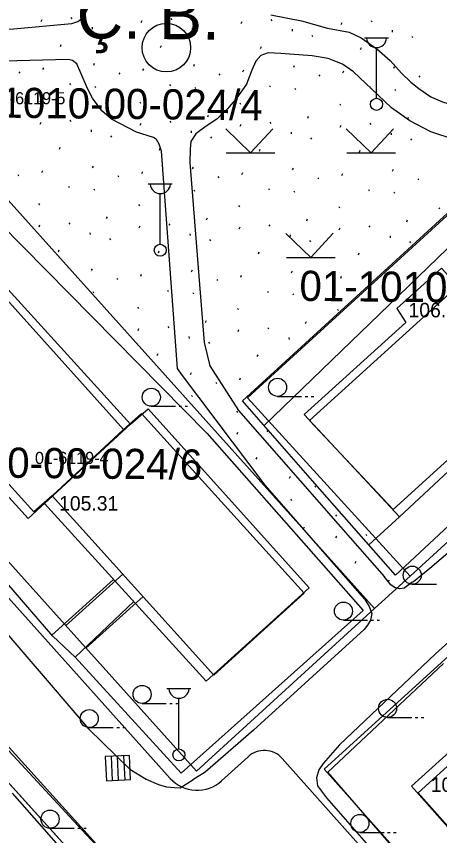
# Model space of a CAD drawing. Extents: x 412225 to 413380, y 4456471 to 4457189.
# Drawn here: x 412615.8 to 412650.9, y 4457061.2 to 4457129.1 of the extents above; entities that cross this region are included whole.
import ezdxf

# ---------------------------------------------------------------- set-up
doc = ezdxf.new("R2010")
doc.units = 0
for name, color, linetype in [('0_HALİHAZIR', 7, 'Continuous'), ('0_KADASTRO', 7, 'Continuous'), ('Level 27', 7, 'Continuous'), ('Level 41', 7, 'Continuous'), ('Level 56', 7, 'Continuous'), ('Level 57', 7, 'Continuous'), ('Level 59', 7, 'Continuous'), ('Level 62', 7, 'Continuous')]:
    doc.layers.add(name, color=color, linetype=linetype)

msp = doc.modelspace()

# ---------------------------------------------------------------- linework, layer by layer
at = {"layer": '0_HALİHAZIR'}
for p, q in [((412644.653, 4457127.279), (412646.653, 4457127.279)), ((412645.653, 4457122.279), (412645.653, 4457126.472)), ((412635.207, 4457117.747), (412633.147, 4457119.737)), ((412635.207, 4457117.747), (412637.057, 4457119.757)), ((412645.207, 4457117.748), (412643.147, 4457119.738)), ((412645.207, 4457117.748), (412647.057, 4457119.758)), ((412633.187, 4457117.747), (412637.227, 4457117.747)), ((412643.187, 4457117.748), (412647.227, 4457117.748)), ((412626.723, 4457115.185), (412628.723, 4457115.185)), ((412627.723, 4457110.185), (412627.723, 4457114.378)), ((412640.208, 4457109.087), (412638.148, 4457111.077)), ((412640.208, 4457109.087), (412642.058, 4457111.098)), ((412638.188, 4457109.087), (412642.228, 4457109.088)), ((412637.447, 4457097.584), (412639.447, 4457097.584)), ((412639.747, 4457097.584), (412639.947, 4457097.584)), ((412640.247, 4457097.584), (412640.447, 4457097.584)), ((412626.98, 4457096.761), (412628.98, 4457096.761)), ((412629.28, 4457096.761), (412629.48, 4457096.761)), ((412629.78, 4457096.761), (412629.98, 4457096.761)), ((412648.619, 4457082.016), (412650.619, 4457082.016)), ((412642.909, 4457079.04), (412644.909, 4457079.04)), ((412645.209, 4457079.04), (412645.409, 4457079.04)), ((412645.709, 4457079.04), (412645.909, 4457079.04)), ((412628.271, 4457073.374), (412630.271, 4457073.374)), ((412629.271, 4457068.374), (412629.271, 4457072.567)), ((412626.215, 4457072.141), (412628.215, 4457072.142)), ((412628.515, 4457072.142), (412628.715, 4457072.142)), ((412629.015, 4457072.142), (412629.215, 4457072.142)), ((412646.57, 4457070.983), (412648.57, 4457070.983)), ((412648.87, 4457070.983), (412649.07, 4457070.983)), ((412649.37, 4457070.983), (412649.57, 4457070.983)), ((412621.832, 4457070.135), (412623.832, 4457070.135)), ((412624.132, 4457070.135), (412624.332, 4457070.135)), ((412624.632, 4457070.135), (412624.832, 4457070.135)), ((412625.164, 4457067.837), (412623.166, 4457067.732)), ((412625.164, 4457067.837), (412623.166, 4457067.732)), ((412624.271, 4457065.787), (412624.165, 4457067.784)), ((412624.818, 4457065.816), (412624.712, 4457067.813)), ((412625.269, 4457065.84), (412625.164, 4457067.837)), ((412625.269, 4457065.84), (412625.164, 4457067.837)), ((412623.166, 4457067.732), (412623.272, 4457065.734)), ((412623.166, 4457067.732), (412623.272, 4457065.734)), ((412623.776, 4457065.761), (412623.67, 4457067.758)), ((412623.272, 4457065.734), (412625.269, 4457065.84)), ((412623.272, 4457065.734), (412625.269, 4457065.84)), ((412618.582, 4457061.803), (412620.582, 4457061.803)), ((412620.882, 4457061.803), (412621.082, 4457061.803)), ((412621.382, 4457061.803), (412621.582, 4457061.803)), ((412644.276, 4457061.448), (412646.276, 4457061.448)), ((412646.576, 4457061.448), (412646.776, 4457061.448)), ((412647.076, 4457061.448), (412647.276, 4457061.448))]:
    msp.add_line(p, q, dxfattribs=at)
for points in [[(412666.722, 4457149.847), (412683.715, 4457130.465), (412688.733, 4457125.108), (412689.962, 4457123.702), (412690.595, 4457122.882), (412690.735, 4457122.493), (412690.726, 4457122.1), (412690.676, 4457121.39), (412690.163, 4457120.297), (412689.764, 4457119.716), (412687.857, 4457117.849), (412679.792, 4457110.22), (412668.162, 4457099.827), (412652.892, 4457085.728), (412650.071, 4457083.307)], [(412586.499, 4457113.505), (412599.497, 4457125.36), (412601.397, 4457126.977), (412602.133, 4457127.316), (412602.666, 4457127.482), (412615.554, 4457128.043), (412620.399, 4457128.469), (412620.895, 4457128.65), (412621.301, 4457128.945), (412621.489, 4457129.276), (412621.709, 4457129.751), (412622.347, 4457130.765), (412623.233, 4457131.631), (412624.368, 4457132.606), (412625.456, 4457133.146), (412626.053, 4457133.394), (412626.466, 4457133.835), (412626.657, 4457134.458), (412626.648, 4457144.638), (412626.453, 4457148.095), (412625.97, 4457149.047)], [(412636.89, 4457129.185), (412639.421, 4457128.686), (412641.594, 4457128.096), (412643.378, 4457127.758), (412644.388, 4457127.291), (412645.679, 4457126.37), (412646.785, 4457125.411), (412647.716, 4457124.363), (412648.493, 4457123.616), (412649.171, 4457123.093), (412650.158, 4457122.408), (412651.134, 4457121.991), (412652.439, 4457121.569), (412653.902, 4457121.37), (412655.306, 4457121.661), (412656.704, 4457122.549), (412667.092, 4457132.24)], [(412571.237, 4457126.583), (412582.789, 4457113.858), (412594.87, 4457100.897), (412607.242, 4457086.936), (412618.505, 4457073.845), (412621.76, 4457070.045)], [(412656.443, 4457091.342), (412647.227, 4457082.781), (412640.333, 4457090.585), (412634.547, 4457097.223), (412666.876, 4457126.785)], [(412644.651, 4457080.814), (412636.43, 4457090.235), (412629.579, 4457099.303), (412629.159, 4457099.886), (412627.822, 4457117.893), (412627.634, 4457118.487), (412627.411, 4457118.876), (412627.164, 4457119.036), (412625.749, 4457119.464), (412623.688, 4457120.559), (412622.872, 4457121.235), (412622.111, 4457122.274), (412621.691, 4457123.088), (412620.8, 4457125.119), (412620.449, 4457125.394), (412620.125, 4457125.484), (412605.091, 4457125.109), (412603.566, 4457124.813), (412601.564, 4457123.567), (412588.315, 4457111.518)], [(412652.173, 4457118.831), (412650.162, 4457119.485), (412648.408, 4457120.406), (412646.907, 4457121.484), (412645.248, 4457123.057), (412643.753, 4457124.475), (412642.836, 4457125.096), (412641.644, 4457125.585), (412640.327, 4457125.789), (412637.72, 4457125.987), (412636.663, 4457126.043), (412636.055, 4457125.832), (412635.653, 4457125.354), (412635.308, 4457124.593), (412634.882, 4457123.446), (412634.08, 4457122.32), (412633.301, 4457121.411), (412632.403, 4457120.545), (412631.52, 4457119.959), (412630.659, 4457119.335), (412630.272, 4457118.698), (412630.191, 4457118.081), (412630.167, 4457116.95), (412630.912, 4457107.534), (412631.365, 4457102.055), (412631.823, 4457100.119), (412634.208, 4457096.413), (412642.673, 4457086.772), (412646.278, 4457082.661)], [(412668.291, 4457125.985), (412636.342, 4457095.163)], [(412610.607, 4457115.774), (412631.597, 4457094.524), (412644.556, 4457079.848), (412629.451, 4457066.363), (412620.68, 4457075.971)], [(412688.789, 4457110.474), (412676.857, 4457100.196), (412663.153, 4457087.564), (412650.553, 4457076.263), (412642.59, 4457068.703), (412641.23, 4457067.176), (412640.87, 4457066.641), (412640.687, 4457065.987), (412640.751, 4457065.319), (412641.497, 4457064.308), (412651.959, 4457052.379)], [(412618.823, 4457077.701), (412607.347, 4457090.959)], [(412662.749, 4457016.406), (412651.562, 4457029.05), (412636.523, 4457045.377), (412621.572, 4457061.282), (412605.727, 4457078.415), (412597.001, 4457088.077)], [(412647.572, 4457087.605), (412645.027, 4457085.271)], [(412650.071, 4457083.307), (412648.709, 4457082.211), (412648.553, 4457082.163)], [(412618.742, 4457077.795), (412623.857, 4457082.42)], [(412648.553, 4457082.163), (412647.968, 4457081.695), (412647.564, 4457081.643), (412647.142, 4457081.739), (412646.838, 4457081.974), (412646.278, 4457082.661)], [(412644.651, 4457080.814), (412645.047, 4457080.166), (412645.263, 4457079.601), (412645.16, 4457079.041), (412644.916, 4457078.623), (412644.639, 4457078.257), (412635.466, 4457069.923), (412631.434, 4457066.459), (412630.426, 4457065.824)], [(412620.68, 4457075.971), (412625.519, 4457080.591)], [(412618.823, 4457077.701), (412620.68, 4457075.971)], [(412654.345, 4457051.812), (412641.626, 4457066.439), (412651.198, 4457075.443)], [(412621.76, 4457070.045), (412625.211, 4457066.702), (412626.558, 4457065.881), (412627.566, 4457065.421), (412628.233, 4457065.239), (412628.893, 4457065.167), (412629.36, 4457065.154), (412630.426, 4457065.824)], [(412615.442, 4457064.702), (412625.563, 4457053.22), (412611.173, 4457039.673), (412592.706, 4457059.584), (412594.529, 4457061.141)]]:
    msp.add_lwpolyline(points, dxfattribs=at)
for points in [[(412611.765, 4457110.092), (412625.266, 4457095.29), (412616.766, 4457087.459), (412603.258, 4457102.358)], [(412654.493, 4457109.584), (412651.817, 4457107.339), (412651.035, 4457108.208), (412647.338, 4457104.848), (412648.093, 4457103.7), (412639.667, 4457096.084), (412647.572, 4457087.605), (412662.236, 4457101.272), (412660.946, 4457102.707)], [(412625.266, 4457095.29), (412626.708, 4457096.541), (412640.062, 4457081.722), (412631.519, 4457073.991), (412618.132, 4457088.717)], [(412663.445, 4457078.735), (412669.857, 4457071.607), (412671.07, 4457070.131), (412656.277, 4457056.58), (412648.567, 4457065.292)]]:
    msp.add_lwpolyline(points, close=True, dxfattribs=at)
for centre, radius in [((412628.231, 4457126.47), 2.009), ((412645.653, 4457121.779), 0.5), ((412627.723, 4457109.685), 0.5), ((412637.447, 4457098.334), 0.75), ((412626.98, 4457097.511), 0.75), ((412648.619, 4457082.766), 0.75), ((412642.909, 4457079.79), 0.75), ((412626.215, 4457072.891), 0.75), ((412646.57, 4457071.733), 0.75), ((412621.832, 4457070.885), 0.75), ((412629.271, 4457067.874), 0.5), ((412618.582, 4457062.553), 0.75), ((412644.276, 4457062.198), 0.75)]:
    msp.add_circle(centre, radius, dxfattribs=at)
for centre in [(412645.653, 4457127.309), (412627.723, 4457115.215), (412629.271, 4457073.403)]:
    msp.add_arc(centre, 0.837, 183.298, 356.90719, dxfattribs=at)
at = {"layer": '0_KADASTRO'}
msp.add_lwpolyline([(412602.001, 4457142.229), (412625.676, 4457149.845), (412628.236, 4457150.669), (412623.56, 4457165.205), (412628.608, 4457159.498), (412642.417, 4457143.887), (412658.161, 4457126.088), (412659.073, 4457125.057), (412673.936, 4457138.44), (412689.844, 4457120.47), (412682.426, 4457113.701), (412681.983, 4457114.187), (412668.946, 4457128.476), (412634.964, 4457097.471), (412647.897, 4457083.297), (412648.445, 4457082.697), (412645.49, 4457080.001), (412613.407, 4457115.704)], dxfattribs=at)
for points in [[(412634.964, 4457097.471), (412668.946, 4457128.476), (412681.983, 4457114.187), (412682.426, 4457113.701), (412648.445, 4457082.697), (412647.897, 4457083.297)], [(412598.633, 4457102.224), (412612.968, 4457115.303), (412613.407, 4457115.704), (412645.49, 4457080.001), (412630.715, 4457066.521), (412613.994, 4457085.129)], [(412641.315, 4457066.687), (412676.859, 4457098.984), (412677.17, 4457098.634), (412690.156, 4457084.044), (412672.943, 4457068.403), (412654.627, 4457051.76), (412641.805, 4457066.138)], [(412576.154, 4457078.845), (412590.151, 4457091.291), (412591.099, 4457092.135), (412625.322, 4457054.321), (412625.104, 4457054.128), (412610.332, 4457040.992), (412593.199, 4457059.967), (412576.633, 4457078.314)]]:
    msp.add_lwpolyline(points, close=True, dxfattribs=at)
at = {"layer": 'Level 27'}
for points in [[(412630.715, 4457066.521), (412613.994, 4457085.129), (412598.633, 4457102.224), (412597.284, 4457103.724), (412561.903, 4457143.098), (412560.367, 4457144.807)], [(412689.844, 4457120.47), (412682.426, 4457113.701), (412648.445, 4457082.697), (412645.49, 4457080.001), (412645.49, 4457080.001), (412630.715, 4457066.521)], [(412641.315, 4457066.687), (412676.859, 4457098.984), (412679.801, 4457101.657), (412694.484, 4457115.229)], [(412592.561, 4457090.519), (412625.322, 4457054.321), (412632.032, 4457046.907), (412649.43, 4457027.697), (412649.43, 4457027.697), (412668.449, 4457006.699), (412669.615, 4457004.71), (412669.079, 4457002.597), (412668.196, 4457000.596), (412654.558, 4456991.925), (412647.057, 4456987.08), (412625.215, 4456972.976), (412617.864, 4456968.23), (412604.785, 4456959.819), (412602.573, 4456958.764), (412600.503, 4456958.758), (412598.437, 4456960.001), (412566.106, 4456995.183), (412565.155, 4456996.219), (412533.021, 4457031.187), (412532.637, 4457031.604)], [(412745.985, 4457051.286), (412744.84, 4457050.509), (412726.191, 4457038.285), (412705.949, 4457025.019), (412705.176, 4457024.512), (412701.293, 4457021.967), (412698.715, 4457020.277), (412686.613, 4457012.33), (412683.807, 4457011.528), (412680.955, 4457012.103), (412678.505, 4457013.338), (412651.296, 4457043.314), (412648.699, 4457046.374), (412649.306, 4457046.925), (412654.025, 4457051.213), (412654.627, 4457051.76), (412641.805, 4457066.138), (412641.315, 4457066.687)]]:
    msp.add_lwpolyline(points, dxfattribs=at)
at = {"layer": 'Level 41'}
for p, q in [((412620.32, 4457128.971), (412620.39, 4457128.863)), ((412628.613, 4457128.886), (412628.683, 4457128.778)), ((412617.852, 4457128.651), (412617.925, 4457128.81)), ((412626.144, 4457128.566), (412626.218, 4457128.725)), ((412634.437, 4457128.481), (412634.511, 4457128.641)), ((412636.905, 4457128.801), (412636.975, 4457128.693)), ((412642.73, 4457128.396), (412642.803, 4457128.556)), ((412645.198, 4457128.716), (412645.268, 4457128.608)), ((412622.07, 4457128.162), (412622.086, 4457128.002)), ((412623.695, 4457127.675), (412623.764, 4457127.567)), ((412630.363, 4457128.077), (412630.379, 4457127.917)), ((412631.988, 4457127.59), (412632.057, 4457127.483)), ((412638.655, 4457127.992), (412638.672, 4457127.832)), ((412640.28, 4457127.505), (412640.349, 4457127.398)), ((412646.948, 4457127.907), (412646.964, 4457127.747)), ((412648.573, 4457127.421), (412648.642, 4457127.313)), ((412619.447, 4457126.575), (412619.52, 4457126.734)), ((412627.739, 4457126.49), (412627.813, 4457126.649)), ((412636.032, 4457126.405), (412636.105, 4457126.564)), ((412644.324, 4457126.32), (412644.398, 4457126.479)), ((412617.989, 4457124.651), (412618.062, 4457124.811)), ((412622.203, 4457125.016), (412622.274, 4457125.176)), ((412630.495, 4457124.931), (412630.567, 4457125.091)), ((412638.788, 4457124.847), (412638.86, 4457125.006)), ((412647.081, 4457124.762), (412647.152, 4457124.921)), ((412615.999, 4457124.464), (412616.069, 4457124.357)), ((412624.291, 4457124.379), (412624.361, 4457124.272)), ((412626.281, 4457124.567), (412626.354, 4457124.726)), ((412632.584, 4457124.294), (412632.654, 4457124.187)), ((412634.574, 4457124.482), (412634.647, 4457124.641)), ((412640.877, 4457124.209), (412640.946, 4457124.102)), ((412642.867, 4457124.397), (412642.939, 4457124.556)), ((412649.169, 4457124.124), (412649.239, 4457124.018)), ((412620.197, 4457123.492), (412620.267, 4457123.384)), ((412622.294, 4457123.278), (412622.364, 4457123.171)), ((412628.49, 4457123.407), (412628.56, 4457123.299)), ((412630.587, 4457123.193), (412630.657, 4457123.086)), ((412636.782, 4457123.322), (412636.852, 4457123.214)), ((412638.879, 4457123.109), (412638.949, 4457123.001)), ((412645.075, 4457123.237), (412645.145, 4457123.129)), ((412647.172, 4457123.024), (412647.242, 4457122.916)), ((412617.726, 4457122.064), (412617.796, 4457121.956)), ((412626.019, 4457121.979), (412626.089, 4457121.871)), ((412634.312, 4457121.894), (412634.381, 4457121.786)), ((412642.604, 4457121.809), (412642.674, 4457121.702)), ((412623.366, 4457120.813), (412623.439, 4457120.971)), ((412631.658, 4457120.728), (412631.731, 4457120.887)), ((412639.951, 4457120.643), (412640.024, 4457120.802)), ((412648.244, 4457120.559), (412648.316, 4457120.717)), ((412617.765, 4457120.141), (412617.838, 4457120.301)), ((412620.233, 4457120.461), (412620.303, 4457120.353)), ((412626.057, 4457120.057), (412626.131, 4457120.216)), ((412628.526, 4457120.376), (412628.596, 4457120.269)), ((412634.35, 4457119.972), (412634.423, 4457120.131)), ((412636.818, 4457120.291), (412636.888, 4457120.184)), ((412642.642, 4457119.887), (412642.716, 4457120.046)), ((412645.111, 4457120.207), (412645.181, 4457120.099)), ((412621.983, 4457119.652), (412621.999, 4457119.492)), ((412630.275, 4457119.567), (412630.292, 4457119.407)), ((412638.568, 4457119.483), (412638.584, 4457119.322)), ((412646.861, 4457119.398), (412646.877, 4457119.237)), ((412623.608, 4457119.166), (412623.677, 4457119.058)), ((412631.901, 4457119.081), (412631.97, 4457118.973)), ((412640.193, 4457118.996), (412640.262, 4457118.888)), ((412648.486, 4457118.911), (412648.555, 4457118.803)), ((412619.36, 4457118.065), (412619.433, 4457118.224)), ((412627.652, 4457117.98), (412627.726, 4457118.139)), ((412635.945, 4457117.895), (412636.018, 4457118.055)), ((412644.237, 4457117.81), (412644.311, 4457117.97)), ((412622.116, 4457116.507), (412622.187, 4457116.666)), ((412615.912, 4457115.954), (412615.982, 4457115.847)), ((412617.902, 4457116.142), (412617.974, 4457116.301)), ((412626.194, 4457116.057), (412626.267, 4457116.216)), ((412630.408, 4457116.422), (412630.48, 4457116.581)), ((412634.487, 4457115.972), (412634.56, 4457116.131)), ((412638.701, 4457116.337), (412638.773, 4457116.496)), ((412642.779, 4457115.887), (412642.852, 4457116.046)), ((412646.993, 4457116.252), (412647.065, 4457116.411)), ((412624.204, 4457115.869), (412624.274, 4457115.763)), ((412632.497, 4457115.784), (412632.567, 4457115.678)), ((412640.789, 4457115.7), (412640.859, 4457115.593)), ((412649.082, 4457115.615), (412649.152, 4457115.508)), ((412620.11, 4457114.982), (412620.18, 4457114.874)), ((412622.207, 4457114.769), (412622.277, 4457114.661)), ((412628.403, 4457114.897), (412628.473, 4457114.79)), ((412630.5, 4457114.684), (412630.569, 4457114.576)), ((412636.695, 4457114.812), (412636.765, 4457114.705)), ((412638.792, 4457114.599), (412638.862, 4457114.491)), ((412644.988, 4457114.728), (412645.058, 4457114.62)), ((412647.085, 4457114.514), (412647.155, 4457114.406)), ((412617.639, 4457113.554), (412617.709, 4457113.447)), ((412625.932, 4457113.47), (412626.002, 4457113.362)), ((412634.224, 4457113.385), (412634.294, 4457113.277)), ((412642.517, 4457113.3), (412642.587, 4457113.192)), ((412650.81, 4457113.215), (412650.879, 4457113.107)), ((412620.146, 4457111.952), (412620.216, 4457111.844)), ((412623.279, 4457112.304), (412623.351, 4457112.462)), ((412631.571, 4457112.219), (412631.644, 4457112.377)), ((412639.864, 4457112.134), (412639.937, 4457112.292)), ((412648.156, 4457112.049), (412648.229, 4457112.207)), ((412617.678, 4457111.632), (412617.751, 4457111.791)), ((412625.97, 4457111.547), (412626.044, 4457111.706)), ((412628.439, 4457111.867), (412628.508, 4457111.759)), ((412634.263, 4457111.462), (412634.336, 4457111.621)), ((412636.731, 4457111.782), (412636.801, 4457111.674)), ((412642.555, 4457111.377), (412642.629, 4457111.537)), ((412645.024, 4457111.697), (412645.094, 4457111.589)), ((412621.896, 4457111.143), (412621.912, 4457110.983)), ((412623.521, 4457110.656), (412623.59, 4457110.548)), ((412630.188, 4457111.058), (412630.205, 4457110.898)), ((412631.814, 4457110.571), (412631.882, 4457110.463)), ((412638.481, 4457110.973), (412638.497, 4457110.813)), ((412646.774, 4457110.888), (412646.79, 4457110.728)), ((412640.106, 4457110.486), (412640.175, 4457110.379)), ((412648.399, 4457110.401), (412648.468, 4457110.294)), ((412619.272, 4457109.555), (412619.346, 4457109.715)), ((412627.565, 4457109.471), (412627.639, 4457109.63)), ((412635.858, 4457109.386), (412635.931, 4457109.545)), ((412644.15, 4457109.301), (412644.224, 4457109.46)), ((412622.029, 4457107.997), (412622.1, 4457108.156)), ((412630.321, 4457107.912), (412630.393, 4457108.072)), ((412638.614, 4457107.827), (412638.685, 4457107.987)), ((412624.117, 4457107.36), (412624.187, 4457107.253)), ((412626.107, 4457107.547), (412626.18, 4457107.707)), ((412632.41, 4457107.275), (412632.48, 4457107.168)), ((412634.4, 4457107.463), (412634.472, 4457107.622)), ((412640.702, 4457107.19), (412640.772, 4457107.083)), ((412642.692, 4457107.378), (412642.765, 4457107.537)), ((412622.12, 4457106.259), (412622.19, 4457106.151)), ((412628.316, 4457106.388), (412628.385, 4457106.28)), ((412630.412, 4457106.174), (412630.482, 4457106.067)), ((412636.608, 4457106.303), (412636.678, 4457106.195)), ((412638.705, 4457106.089), (412638.775, 4457105.982)), ((412625.845, 4457104.96), (412625.915, 4457104.852)), ((412634.137, 4457104.875), (412634.207, 4457104.767)), ((412642.43, 4457104.79), (412642.5, 4457104.683)), ((412631.484, 4457103.709), (412631.557, 4457103.867)), ((412639.777, 4457103.624), (412639.849, 4457103.783)), ((412625.883, 4457103.037), (412625.957, 4457103.197)), ((412628.351, 4457103.357), (412628.421, 4457103.25)), ((412634.176, 4457102.953), (412634.249, 4457103.112)), ((412636.644, 4457103.272), (412636.714, 4457103.165)), ((412630.101, 4457102.548), (412630.118, 4457102.388)), ((412638.394, 4457102.463), (412638.41, 4457102.303)), ((412631.726, 4457102.062), (412631.795, 4457101.954)), ((412627.478, 4457100.961), (412627.552, 4457101.12)), ((412635.77, 4457100.876), (412635.844, 4457101.035)), ((412630.234, 4457099.403), (412630.306, 4457099.562)), ((412634.313, 4457098.953), (412634.385, 4457099.112)), ((412632.323, 4457098.765), (412632.393, 4457098.659)), ((412630.325, 4457097.665), (412630.395, 4457097.557)), ((412634.05, 4457096.366), (412634.12, 4457096.258)), ((412634.089, 4457094.443), (412634.162, 4457094.602)), ((412636.557, 4457094.763), (412636.627, 4457094.655)), ((412635.683, 4457092.367), (412635.757, 4457092.526)), ((412638.44, 4457090.808), (412638.511, 4457090.968)), ((412640.528, 4457090.171), (412640.598, 4457090.064)), ((412638.531, 4457089.07), (412638.601, 4457088.963)), ((412642.256, 4457087.771), (412642.326, 4457087.663)), ((412639.603, 4457086.605), (412639.675, 4457086.763)), ((412644.762, 4457086.168), (412644.832, 4457086.061)), ((412642.294, 4457085.849), (412642.368, 4457086.008)), ((412643.889, 4457083.772), (412643.962, 4457083.931)), ((412646.645, 4457082.214), (412646.717, 4457082.373))]:
    msp.add_line(p, q, dxfattribs=at)
at = {"layer": 'Level 57'}
for points in [[(412648.445, 4457082.697), (412647.897, 4457083.297), (412634.964, 4457097.471), (412668.946, 4457128.476), (412681.983, 4457114.187), (412682.426, 4457113.701)], [(412598.633, 4457102.224), (412612.968, 4457115.303), (412613.407, 4457115.704), (412645.49, 4457080.001)]]:
    msp.add_lwpolyline(points, dxfattribs=at)
at = {"layer": 'Level 59'}
for p, q in [((412624.624, 4457082.847), (412619.877, 4457078.582)), ((412626.298, 4457080.99), (412621.548, 4457076.722))]:
    msp.add_line(p, q, dxfattribs=at)
for points in [[(412603.78, 4457102.867), (412611.304, 4457109.685), (412624.687, 4457094.85), (412618.76, 4457089.352), (412617.237, 4457088.024)], [(412640.103, 4457095.573), (412654.923, 4457109.007), (412660.463, 4457103.031), (412661.853, 4457101.653), (412647.033, 4457088.219)], [(412655.822, 4457057.2), (412649.121, 4457064.735), (412663.898, 4457078.167), (412669.363, 4457072.25), (412670.706, 4457070.727)]]:
    msp.add_lwpolyline(points, close=True, dxfattribs=at)
msp.add_lwpolyline([(412624.687, 4457094.85), (412626.172, 4457096.171), (412639.657, 4457081.271), (412632.162, 4457074.485), (412618.76, 4457089.352)], dxfattribs=at)
at = {"layer": 'Level 62'}
for points in [[(412628.553, 4457065.934), (412612.506, 4457083.792), (412597.146, 4457100.887), (412595.797, 4457102.387), (412560.558, 4457141.603)], [(412594.051, 4457091.854), (412626.805, 4457055.663), (412633.515, 4457048.249), (412650.912, 4457029.04), (412669.366, 4457008.666)], [(412635.001, 4457067.724), (412632.807, 4457065.723)], [(412650.497, 4457053.387), (412637.842, 4457067.578)]]:
    msp.add_lwpolyline(points, dxfattribs=at)
for centre, radius, start, end in [((412636.349, 4457066.247), 2, 41.72667, 132.38779), ((412630.785, 4457067.939), 3, 221.94156, 312.37437)]:
    msp.add_arc(centre, radius, start, end, dxfattribs=at)

# ---------------------------------------------------------------- texts
at = {"layer": '0_HALİHAZIR'}
for s, p in [('106.35', (412648.309, 4457104.13)), ('105.31', (412619.335, 4457088.117)), ('106.12', (412650.15, 4457064.81))]:
    msp.add_text(s, height=1.2, dxfattribs=at).set_placement(p)
at = {"layer": '0_KADASTRO'}
for s, p in [('01-6119-5', (412613.756, 4457121.783)), ('01-6119-5', (412613.756, 4457121.783)), ('01-6119-4', (412617.337, 4457091.98)), ('01-6119-4', (412617.337, 4457091.98))]:
    msp.add_text(s, height=1, dxfattribs=at).set_placement(p)
at = {"layer": 'Level 41'}
msp.add_text('Ç. B.', height=4, rotation=359.4141, dxfattribs=at).set_placement((412620.773, 4457127.252))
at = {"layer": 'Level 56'}
for s, p in [('01-1010-00-024/4', (412609.629, 4457120.72)), ('01-1010-00-024/5', (412639.254, 4457105.496)), ('01-1010-00-024/6', (412604.613, 4457090.948))]:
    msp.add_text(s, height=2.5, rotation=359.4136, dxfattribs=at).set_placement(p)

doc.saveas('drawing.dxf')
